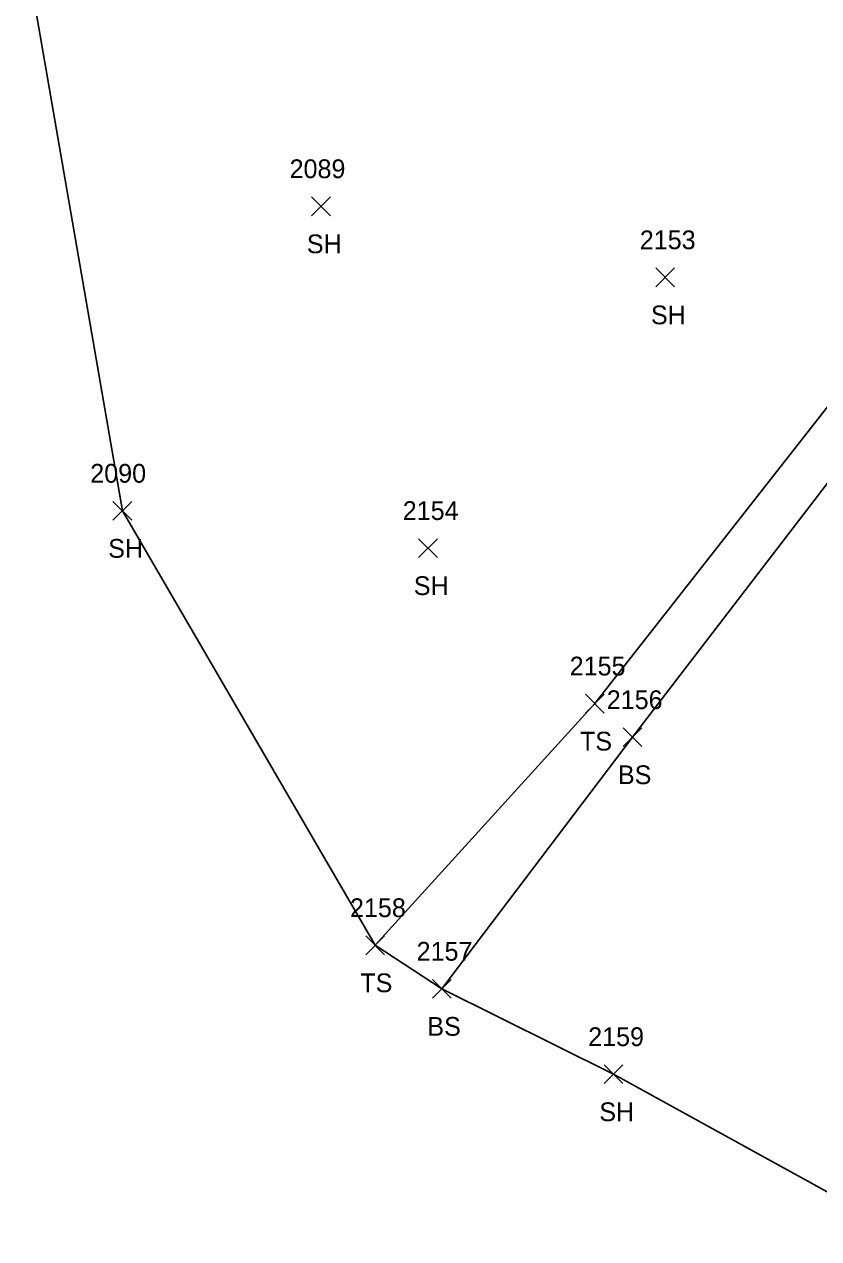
# Model space of a CAD drawing. Extents: x 1459992 to 1461532, y 647785 to 648535.
# Drawn here: x 1461033.2 to 1461117.9, y 648072 to 648201.4 of the extents above; entities that cross this region are included whole.
import ezdxf

# ---------------------------------------------------------------- set-up
doc = ezdxf.new("R2010")
doc.units = 0
for name, color, linetype in [('L_A', 7, 'Continuous'), ('L_I', 7, 'Continuous'), ('L_TIC', 7, 'Continuous'), ('LELB', 7, 'Continuous'), ('LSOGP', 7, 'Continuous')]:
    doc.layers.add(name, color=color, linetype=linetype)

msp = doc.modelspace()

# ---------------------------------------------------------------- linework, layer by layer
at = {"layer": 'L_TIC'}
for points in [[(1461063.82, 648181.03), (1461065.82, 648183.03)], [(1461065.82, 648181.03), (1461063.82, 648183.03)], [(1461100.49, 648173.46), (1461102.49, 648175.46)], [(1461102.49, 648173.46), (1461100.49, 648175.46)], [(1461042.65, 648148.58), (1461044.65, 648150.58)], [(1461044.65, 648148.58), (1461042.65, 648150.58)], [(1461075.22, 648144.61), (1461077.22, 648146.61)], [(1461077.22, 648144.61), (1461075.22, 648146.61)], [(1461093.01, 648128.04), (1461095.01, 648130.04)], [(1461095.01, 648128.04), (1461093.01, 648130.04)], [(1461097.02, 648124.46), (1461099.02, 648126.46)], [(1461099.02, 648124.46), (1461097.02, 648126.46)], [(1461069.6, 648102.29), (1461071.6, 648104.29)], [(1461071.6, 648102.29), (1461069.6, 648104.29)], [(1461076.7, 648097.65), (1461078.7, 648099.65)], [(1461078.7, 648097.65), (1461076.7, 648099.65)], [(1461094.99, 648088.55), (1461096.99, 648090.55)], [(1461096.99, 648088.55), (1461094.99, 648090.55)]]:
    msp.add_lwpolyline(points, dxfattribs=at)
at = {"layer": 'LELB'}
for points in [[(1461170.36, 648220.98), (1461142.74, 648192.43), (1461120.86, 648163.3), (1461094.01, 648129.04), (1461070.6, 648103.29)], [(1461170.36, 648220.98), (1461146.74, 648189.22), (1461125.11, 648160.77), (1461098.02, 648125.46), (1461077.7, 648098.65)]]:
    msp.add_lwpolyline(points, dxfattribs=at)
at = {"layer": 'LSOGP'}
msp.add_lwpolyline([(1461033.2, 648210.12), (1461043.65, 648149.58), (1461070.6, 648103.29), (1461077.7, 648098.65), (1461095.99, 648089.55), (1461127.84, 648072.03)], dxfattribs=at)

# ---------------------------------------------------------------- texts
at = {"layer": 'L_A'}
for s, p in [('SH', (1461063.31, 648177.03)), ('SH', (1461099.98, 648169.46)), ('SH', (1461042.14, 648144.58)), ('SH', (1461074.71, 648140.61)), ('TS', (1461092.42, 648124.04)), ('BS', (1461096.46, 648120.46)), ('TS', (1461069.01, 648098.29)), ('BS', (1461076.15, 648093.65)), ('SH', (1461094.48, 648084.55))]:
    msp.add_text(s, height=2, dxfattribs=at).set_placement(p)
at = {"layer": 'L_I'}
for s, p in [('2089', (1461061.47, 648185.03)), ('2153', (1461098.79, 648177.46)), ('2090', (1461040.23, 648152.58)), ('2154', (1461073.53, 648148.61)), ('2155', (1461091.32, 648132.04)), ('2156', (1461095.27, 648128.46)), ('2158', (1461067.91, 648106.29)), ('2157', (1461075.01, 648101.65)), ('2159', (1461093.29, 648092.55))]:
    msp.add_text(s, height=2, dxfattribs=at).set_placement(p)

doc.saveas('drawing.dxf')
